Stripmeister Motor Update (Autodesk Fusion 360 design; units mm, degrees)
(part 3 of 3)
sketch "Sketch1" plane through (197.8083, 0, 0) normal (1, 0, 0) x axis (0, 1, 0)
  line L1 (0, 22.5) -> (0, 0)
  line L2 (3.5, 22.2261) -> (0, 0)
  line L3 (-3.5, 22.2261) -> (0, 0)
  circle C1 centre (0, 0) radius 17.907
  circle C2 centre (0, 0) radius 5.3594
  circle C3 centre (0, 0) radius 17.907
  circle C4 centre (0, 0) radius 18.669
  circle C5 centre (0, 0) radius 17.907
  circle C6 centre (0, 0) radius 22.5
  circle C7 centre (0, 0) radius 21.25
  point P5 (0, 0)
  point P7 (0, 0)
  point P8 (0, 22.5)
  point P3 (0, 0)
  point P9 (0, 0)
  point P10 (3.5, 22.2261)
  point P11 (0, 0)
  point P12 (-3.5, 22.2261)
  concentric C3 C6
  concentric C3 C7
  coincident P5 P7
  vertical L1
  coincident C6 P8
  coincident P3 P9
  coincident C6 P10
  coincident P5 P11
  coincident C6 P12
  dimension "d375" diameter C6 = 45
  dimension "d376" diameter C7 = 42.5
  dimension "d382" distance P8 P10 = 3.5
  dimension "d383" distance P8 P12 = 3.5
extrude "Extrude1" add sketch "Sketch1" profile of C6 C7 to an object from offset -30.5
extrude "Extrude2" add sketch "Sketch1" profile of C1 C3 C4 C5 C7 against normal blind 66
extrude "Extrude3" cut sketch "Sketch1" profile of C6 C7 L2 L3 against normal blind 66
sketch "Sketch1" plane through (0, 0, -12.7) normal (0, 0, -1) x axis (1, 0, 0)
  line L1 (12.7, 0.6112) -> (12.7, 32.7422)
  line L2 (-7.9375, -4.1513) -> (7.9375, -4.1513)
  line L3 (-12.7, 32.7422) -> (-12.7, 0.6112)
  line L4 (7.9375, 37.5047) -> (-7.9375, 37.5047)
  line L5 (-38.1, -66.8734) -> (-38.1, 66.8734)
  line L6 (38.1, 66.8734) -> (38.1, -66.8734)
  line L7 (-38.1, 74.7479) -> (-38.1, 66.8734)
  line L8 (-29.1639, 74.7479) -> (-38.1, 74.7479)
  line L9 (261.9, 74.7479) -> (-38.1, 74.7479)
  line L10 (261.9, -74.8109) -> (261.9, 74.7479)
  line L11 (-38.1, -74.8109) -> (261.9, -74.8109)
  line L12 (-38.1, 74.7479) -> (-38.1, -74.8109)
  arc A1 centre (7.9375, 0.6112) radius 4.7625 clockwise from (12.7, 0.6112) to (7.9375, -4.1513)
  arc A2 centre (-7.9375, 0.6112) radius 4.7625 clockwise from (-7.9375, -4.1513) to (-12.7, 0.6112)
  arc A3 centre (-7.9375, 32.7422) radius 4.7625 clockwise from (-12.7, 32.7422) to (-7.9375, 37.5047)
  arc A4 centre (7.9375, 32.7422) radius 4.7625 clockwise from (7.9375, 37.5047) to (12.7, 32.7422)
  circle C1 centre (0, -62.4919) radius 3.9687
  circle C2 centre (-28.575, 65.2859) radius 3.9687
  circle C3 centre (28.575, 65.2859) radius 3.9687
  circle C4 centre (0, -14.8669) radius 5.1594
  circle C5 centre (-22.225, 25.4) radius 5.1594
  circle C6 centre (-22.225, -25.4) radius 5.1594
  circle C7 centre (22.225, 25.4) radius 5.1594
  circle C8 centre (22.225, -25.4) radius 5.1594
  arc A5 centre (30.1625, 66.8734) radius 7.9375 clockwise from (29.1639, 74.7479) to (38.1, 66.8734)
  arc A6 centre (0, 304.7074) radius 231.8015 clockwise from (29.1639, 74.7479) to (-29.1639, 74.7479)
  arc A7 centre (-30.1625, 66.8734) radius 7.9375 clockwise from (-38.1, 66.8734) to (-29.1639, 74.7479)
  arc A8 centre (-30.1625, -66.8734) radius 7.9375 clockwise from (-29.1639, -74.7479) to (-38.1, -66.8734)
  arc A9 centre (0, -304.7074) radius 231.8015 clockwise from (-29.1639, -74.7479) to (29.1639, -74.7479)
  arc A10 centre (30.1625, -66.8734) radius 7.9375 clockwise from (38.1, -66.8734) to (29.1639, -74.7479)
  point P27 (-38.1, 66.8734)
  point P36 (-38.1, 66.8734)
  point P25 (-29.1639, 74.7479)
  point P38 (-29.1639, 74.7479)
  coincident P27 P36
  tangent A7 L7
  coincident P25 P38
  perpendicular L5 L8
  horizontal L9
  vertical L10
  horizontal L11
  vertical L12
  tangent A8 L11
  dimension "d386" distance L10 L12 = 300
extrude "Extrude1" new body sketch "Sketch1" profile of C1 C2 C3 L5 L9 L10 L11 L12 along normal blind 4
sketch "Sketch2" plane through (261.9, 0, 0) normal (1, 0, 0) x axis (0, 1, 0)
  line L1 (-74.7479, -12.7) -> (74.8109, -12.7)
  line L2 (-74.7479, -16.7) -> (-74.7479, -12.7)
  line L3 (74.8109, -16.7) -> (-74.7479, -16.7)
  line L4 (74.8109, -12.7) -> (74.8109, -16.7)
  line L5 (-3.5, 60.3261) -> (-3.3056, 59.0913)
  line L6 (3.3056, 59.0913) -> (3.5, 60.3261)
  line L7 (2.1583, 58.2346) -> (2.6644, 61.4485)
  line L8 (-2.6644, 61.4485) -> (-2.1583, 58.2346)
  line L9 (26, 38.1) -> (0, 38.1)
  line L10 (-26, 38.1) -> (0, 38.1)
  line L11 (-26, -12.7) -> (-26, 38.1)
  line L12 (26, -12.7) -> (26, 38.1)
  arc A1 centre (0, 38.1) radius 22.5 clockwise from (3.5, 60.3261) to (-3.5, 60.3261)
  arc A2 centre (0, 38.1) radius 21.25 clockwise from (3.3056, 59.0913) to (-3.3056, 59.0913)
  arc A3 centre (0, 38.1) radius 20.25 clockwise from (2.1583, 58.2346) to (-2.1583, 58.2346)
  arc A4 centre (0, 38.1) radius 23.5 clockwise from (2.6644, 61.4485) to (-2.6644, 61.4485)
  circle C1 centre (0, 38.1) radius 21.875
  circle C2 centre (0, 38.1) radius 1.5875
  circle C3 centre (0, 38.1) radius 23.5
  circle C4 centre (0, 38.1) radius 26
  point P16 (-2.6644, 61.4485)
  point P19 (0, 38.1)
  point P21 (0, 38.1)
  point P22 (26, 38.1)
  point P9 (0, 38.1)
  point P23 (0, 38.1)
  point P24 (-26, 38.1)
  point P25 (-26, -12.7)
  point P26 (26, -12.7)
  concentric A1 C1
  concentric A1 C3
  coincident P16 C3
  concentric C2 C4
  coincident P19 P21
  coincident C4 P22
  horizontal L9
  coincident P9 P23
  coincident C4 P24
  parallel L9 L10
  coincident L1 P25
  perpendicular L1 L11
  coincident L1 P26
  tangent C4 L12
  dimension "d389" = 1
  dimension "d390" diameter C1 = 43.75
  dimension "d391" diameter C4 = 52
extrude "Extrude2" sketch "Sketch2" profile of L1 L8 A4 L7 C1 C3 C4 L11 L12 blind -60
sketch "Sketch3" plane through (229.5433, 0, 0) normal (1, 0, 0) x axis (0, 1, 0)
  line L1 (-2.4114, 59.8417) -> (-2.6644, 61.4485)
  line L2 (2.6644, 61.4485) -> (2.4114, 59.8417)
  line L3 (26, -12.7) -> (-26, -12.7)
  line L4 (26, 38.1) -> (26, -12.7)
  line L5 (-26, -12.7) -> (-26, 38.1)
  line L6 (50, -12.7) -> (26, -12.7)
  line L7 (50, -6.7) -> (50, -12.7)
  line L8 (26, -6.7) -> (50, -6.7)
  line L9 (26, -12.7) -> (26, -6.7)
  line L10 (-50, -12.7) -> (-26, -12.7)
  line L11 (-50, -6.7) -> (-50, -12.7)
  line L12 (-26, -6.7) -> (-50, -6.7)
  line L13 (-26, -12.7) -> (-26, -6.7)
  line L14 (-30, -16.7) -> (-30, 38.1)
  line L15 (30, -16.7) -> (-30, -16.7)
  line L16 (30, 38.1) -> (30, -16.7)
  arc A1 centre (0, 38.1) radius 21.875 clockwise from (-2.4114, 59.8417) to (2.4114, 59.8417)
  arc A2 centre (0, 38.1) radius 23.5 clockwise from (2.6644, 61.4485) to (-2.6644, 61.4485)
  arc A3 centre (0, 38.1) radius 26 clockwise from (-26, 38.1) to (26, 38.1)
  arc A4 centre (0, 38.1) radius 30 clockwise from (-30, 38.1) to (30, 38.1)
  point P8 (26, -12.7)
  point P11 (26, -12.7)
  point P7 (-26, -12.7)
  point P15 (-26, -12.7)
  point P12 (50, -12.7)
  point P14 (26, -6.7)
  point P16 (-50, -12.7)
  point P18 (-26, -6.7)
  horizontal L6
  vertical L7
  horizontal L8
  vertical L9
  coincident P8 P11
  horizontal L10
  vertical L11
  horizontal L12
  vertical L13
  coincident P7 P15
  dimension "d395" distance P11 P12 = 24
  dimension "d396" distance P11 P14 = 6
  dimension "d397" distance P15 P16 = 24
  dimension "d398" distance P15 P18 = 6
  dimension "d399" = 4
extrude "Extrude3" add sketch "Sketch3" profile of L4 A3 L5 L6 L7 L8 L9 L10 L11 L12 L13 A4 L16 L14 against normal blind 60
sketch "Sketch4" plane through (0, 0, -6.7) normal (0, 0, 1) x axis (-1, 0, 0)
  line L1 (-229.5433, -50) -> (-229.5433, -30)
  line L2 (-169.5433, -50) -> (-229.5433, -50)
  line L3 (-169.5433, -30) -> (-169.5433, -50)
  line L4 (-229.5433, -30) -> (-169.5433, -30)
  line L5 (-229.5433, 30) -> (-229.5433, 50)
  line L6 (-169.5433, 30) -> (-229.5433, 30)
  line L7 (-169.5433, 50) -> (-169.5433, 30)
  line L8 (-229.5433, 50) -> (-169.5433, 50)
  line L9 (-199.5433, -50) -> (-199.5433, 50)
  line L10 (-230, 0) -> (-199.5433, 0)
  line L11 (-169.0866, 0) -> (-199.5433, 0)
  circle C1 centre (-217.5433, 42.5) radius 4
  circle C2 centre (-217.5433, 42.5) radius 7.5
  circle C3 centre (-181.5433, 42.5) radius 4
  circle C4 centre (-181.5433, 42.5) radius 7.5
  circle C5 centre (-181.5433, -42.5) radius 4
  circle C6 centre (-181.5433, -42.5) radius 7.5
  circle C7 centre (-217.5433, -42.5) radius 4
  circle C8 centre (-217.5433, -42.5) radius 7.5
  point P12 (-199.5433, 50)
  point P13 (-199.5433, -50)
  point P14 (-199.5433, 0)
  point P16 (-199.5433, 0)
  point P15 (-230, 0)
  point P17 (-169.0866, 0)
  point P11 (-217.5433, 42.5)
  concentric C1 C2
  tangent L8 C2
  midpoint L8 P12
  midpoint L2 P13
  midpoint L9 P14
  perpendicular L9 L10
  symmetric C1 L9 C3
  symmetric C2 L9 C4
  symmetric L9 P14 P16
  symmetric L9 P15 P17
  symmetric C1 L10 C7
  symmetric C2 L10 C8
  symmetric L10 C3 C5
  symmetric L10 C4 C6
  dimension "d402" diameter C1 = 8
  dimension "d403" diameter C2 = 15
  dimension "d404" distance L5 P11 = 12
extrude "Extrude4" cut sketch "Sketch4" profile of C1 C3 C5 C7 against normal blind 10
offset_faces "OffsetFaces1" distance 4
extrude "Extrude5" cut sketch "Sketch4" profile of C1 C2 C3 C4 C5 C6 C7 C8 against normal blind 2
sketch "Sketch5" plane through (229.5433, 0, 0) normal (1, 0, 0) x axis (0, 1, 0)
  line L1 (-2.4114, 59.8417) -> (-2.6644, 61.4485)
  line L2 (2.6644, 61.4485) -> (2.4114, 59.8417)
  line L3 (54, -12.7) -> (-54, -12.7)
  line L4 (54, -6.7) -> (54, -12.7)
  line L5 (30, -6.7) -> (54, -6.7)
  line L6 (30, 38.1) -> (30, -6.7)
  line L7 (-30, -6.7) -> (-30, 38.1)
  line L8 (-54, -6.7) -> (-30, -6.7)
  line L9 (-54, -12.7) -> (-54, -6.7)
  line L10 (50, -6.7) -> (35, -6.7)
  line L11 (50, -6.7) -> (35, -6.7)
  line L12 (54, -6.7) -> (30, -6.7)
  line L13 (30, -6.7) -> (54, -6.7)
  line L14 (0, -12.7) -> (0, 38.1)
  arc A1 centre (0, 38.1) radius 21.875 clockwise from (-2.4114, 59.8417) to (2.4114, 59.8417)
  arc A2 centre (0, 38.1) radius 23.5 clockwise from (2.6644, 61.4485) to (-2.6644, 61.4485)
  arc A3 centre (0, 38.1) radius 30 clockwise from (-30, 38.1) to (30, 38.1)
  arc A4 centre (233.204, 38.1) radius 203.204 clockwise from (35, -6.7) to (30, 38.1)
  arc A5 centre (-233.204, 38.1) radius 203.204 clockwise from (-30, 38.1) to (-35, -6.7)
  point P11 (30, 38.1)
  point P20 (30, 38.1)
  point P15 (35, -6.7)
  point P19 (35, -6.7)
  point P5 (0, 38.1)
  point P22 (0, 38.1)
  point P26 (-35, -6.7)
  point P25 (-30, 38.1)
  tangent L6 A4
  coincident P11 P20
  coincident P15 P19
  coincident P5 P22
  perpendicular L3 L14
  symmetric P19 L14 P26
  symmetric P20 L14 P25
  symmetric A4 L14 A5
extrude "Extrude6" add sketch "Sketch5" profile of L5 L6 L7 L8 L12 L13 A4 A5 against normal blind 60
fillet "Fillet1" radius 8
work_plane "WorkPlane1"
work_plane "WorkPlane2" AlongDistance 2
work_plane "WorkPlane1" AlongDistance -61
work_plane "WorkPlane2" AlongDistance -29
work_plane "WorkPlane3" AlongDistance -11
split "Split1"
align "Align1"
extrude "Extrude4" add of existing geometry blind 22
sketch "Sketch2" plane through (167.3083, 0, 0) normal (1, 0, 0) x axis (0, 1, 0)
  line L1 (-2.4114, 21.7417) -> (-2.6644, 23.3485)
  line L2 (2.6644, 23.3485) -> (2.4114, 21.7417)
  line L3 (-46, -50.8) -> (-46, -44.8)
  line L4 (46, -50.8) -> (-46, -50.8)
  line L5 (46, -44.8) -> (46, -50.8)
  line L6 (35, -44.8) -> (46, -44.8)
  line L7 (-46, -44.8) -> (-35, -44.8)
  line L8 (-54, -50.8) -> (-46, -50.8)
  line L9 (-46, -50.8) -> (46, -50.8)
  line L10 (46, -50.8) -> (54, -50.8)
  line L11 (-46, -44.8) -> (-54, -44.8)
  line L12 (-54, -44.8) -> (-54, -50.8)
  line L13 (-2.6644, 23.3485) -> (-2.4114, 21.7417)
  line L14 (2.4114, 21.7417) -> (2.6644, 23.3485)
  line L15 (-35, -44.8) -> (-46, -44.8)
  line L16 (46, -44.8) -> (35, -44.8)
  line L17 (54, -50.8) -> (54, -44.8)
  line L18 (54, -44.8) -> (46, -44.8)
  line L19 (27.1878, 12.6817) -> (54, -44.8)
  line L20 (-27.1878, 12.6817) -> (-54, -44.8)
  arc A1 centre (0, 0) radius 21.875 clockwise from (-2.4114, 21.7417) to (2.4114, 21.7417)
  arc A2 centre (0, 0) radius 23.5 clockwise from (2.6644, 23.3485) to (-2.6644, 23.3485)
  arc A3 centre (233.204, 0) radius 203.204 clockwise from (35, -44.8) to (30, 0)
  arc A4 centre (0, 0) radius 30 clockwise from (-30, 0) to (30, 0)
  arc A5 centre (-233.204, 0) radius 203.204 clockwise from (-30, 0) to (-35, -44.8)
  arc A6 centre (0, 0) radius 23.5 clockwise from (2.6644, 23.3485) to (-2.6644, 23.3485)
  arc A7 centre (0, 0) radius 21.875 clockwise from (-2.4114, 21.7417) to (2.4114, 21.7417)
  arc A8 centre (-233.204, 0) radius 203.204 clockwise from (-30, 0) to (-35, -44.8)
  arc A9 centre (0, 0) radius 30 clockwise from (-30, 0) to (30, 0)
  arc A10 centre (233.204, 0) radius 203.204 clockwise from (35, -44.8) to (30, 0)
  point P35 (54, -44.8)
  point P36 (54, -44.8)
  point P37 (27.1878, 12.6817)
  point P21 (-54, -44.8)
  point P38 (-54, -44.8)
  point P39 (-27.1878, 12.6817)
  coincident P35 P36
  coincident A4 P37
  tangent A4 L19
  coincident P21 P38
  coincident A4 P39
  tangent A4 L20
extrude "Extrude7" sketch "Sketch2" profile of L6 A3 A4 A5 L7 L11 L15 A8 A9 A10 L16 L18 L19 L20 blind 3
base_feature "Base Feature1" bodies "Motor", "Gearbox", "Chuck Bottom", "Chuck Top"
base_feature "Base Feature1" bodies "Mount Spacer Stripmeister", "Mount Spacer"
base_feature "Base Feature1" bodies "Drill Motor Train Mount v1", "Drill Motor Train Mount v2 Standoff"
base_feature "Base Feature1" bodies "B Half", "B Half (1)"
base_feature "Base Feature1" bodies "Mount Plate Bracket C v2", "Mount Plate Bracket C"
place_component sketch "Sketch1"
base_feature "Base Feature1" sketch "Sketch1" bodies "Mount Plate Bracket D"
base_feature "Base Feature1"
delete_face "DeleteFace1"
delete_face "DeleteFace2"
position "Position11"
extrude "Extrude1" new body of existing geometry blind 4
offset_faces "OffsetFaces1" distance 4
combine "Combine1"
as_built_joint "As-built2"
position "Position12"
position "Position13"
extrude "Extrude2" cut of existing geometry blind -2.304
delete_face "DeleteFace1"
delete_face "DeleteFace2"
delete_face "DeleteFace3"
delete_face "DeleteFace4"
sketch "Sketch6" plane through (0, 0, -16.7) normal (0, 0, -1) x axis (1, 0, 0)
  line L1 (133.575, 45.6447) -> (133.575, 31.25)
  line L2 (133.575, 45.6447) -> (195.575, 45.6447)
  line L3 (195.575, -45.6447) -> (195.575, 45.6447)
  line L4 (133.575, 31.25) -> (133.575, -31.25)
  line L5 (195.575, -45.6447) -> (133.575, -45.6447)
  line L6 (133.575, -45.6447) -> (133.575, -31.25)
  circle C1 centre (164.575, -37.6447) radius 2
  circle C2 centre (164.575, 37.6447) radius 2
  circle C3 centre (144.575, -37.6447) radius 2
  circle C4 centre (144.575, 37.6447) radius 2
extrude "Extrude8" cut sketch "Sketch6" profile of C1 C2 C3 C4 against normal blind 4
offset_faces "OffsetFaces2" distance -1
sketch "Sketch7" plane through (0, 0, -15.7) normal (0, 0, -1) x axis (1, 0, 0)
  line L1 (-38.1, 74.7479) -> (-38.1, -74.8109)
  line L2 (261.9, 74.7479) -> (-38.1, 74.7479)
  line L3 (261.9, -74.8109) -> (261.9, 74.7479)
  line L4 (-38.1, -74.8109) -> (261.9, -74.8109)
  line L5 (129.575, 37.6447) -> (144.575, 37.6447)
  line L6 (129.575, -37.6447) -> (144.575, -37.6447)
  line L7 (184.575, 35.6447) -> (129.575, 35.6447)
  line L8 (129.575, 39.6447) -> (184.575, 39.6447)
  line L9 (184.575, 37.6447) -> (129.575, 37.6447)
  line L10 (184.575, -39.6447) -> (129.575, -39.6447)
  line L11 (129.575, -35.6447) -> (184.575, -35.6447)
  line L12 (184.575, -37.6447) -> (129.575, -37.6447)
  line L13 (-31.75, -68.4609) -> (255.55, -68.4609)
  line L14 (-31.75, 68.3979) -> (-31.75, -68.4609)
  line L15 (255.55, 68.3979) -> (-31.75, 68.3979)
  line L16 (255.55, -68.4609) -> (255.55, 68.3979)
  line L17 (-28.575, 65.2859) -> (28.575, 65.2859)
  line L18 (0, 30) -> (0, 65.2859)
  circle C1 centre (144.575, -37.6447) radius 2
  circle C2 centre (164.575, -37.6447) radius 2
  circle C3 centre (164.575, 37.6447) radius 2
  circle C4 centre (144.575, 37.6447) radius 2
  circle C5 centre (-28.575, 65.2859) radius 3.9687
  circle C6 centre (28.575, 65.2859) radius 3.9687
  circle C7 centre (0, -62.4919) radius 3.9687
  arc A1 centre (184.575, 37.6447) radius 2 clockwise from (184.575, 39.6447) to (184.575, 35.6447)
  arc A2 centre (129.575, 37.6447) radius 2 clockwise from (129.575, 35.6447) to (129.575, 39.6447)
  arc A3 centre (184.575, -37.6447) radius 2 clockwise from (184.575, -35.6447) to (184.575, -39.6447)
  arc A4 centre (129.575, -37.6447) radius 2 clockwise from (129.575, -39.6447) to (129.575, -35.6447)
  circle C8 centre (242.85, 55.6979) radius 12.7
  circle C9 centre (242.85, -55.7609) radius 12.7
  circle C10 centre (-19.05, -55.7609) radius 12.7
  circle C11 centre (0, 55.6979) radius 12.7
  circle C12 centre (0, 55.6979) radius 2
  circle C13 centre (-19.05, -55.7609) radius 2
  circle C14 centre (242.85, -55.7609) radius 2
  circle C15 centre (242.85, 55.6979) radius 2
  point P5 (144.575, 37.6447)
  point P13 (144.575, 37.6447)
  point P2 (144.575, -37.6447)
  point P15 (144.575, -37.6447)
  point P14 (129.575, 37.6447)
  point P21 (129.575, 37.6447)
  point P16 (129.575, -37.6447)
  point P27 (129.575, -37.6447)
  point P7 (28.575, 65.2859)
  point P37 (28.575, 65.2859)
  point P6 (-28.575, 65.2859)
  point P38 (-28.575, 65.2859)
  point P39 (0, 65.2859)
  point P32 (0, 55.6979)
  point P28 (184.575, -37.6447)
  point P4 (164.575, 37.6447)
  point P22 (184.575, 37.6447)
  coincident P5 P13
  horizontal L5
  coincident P2 P15
  horizontal L6
  tangent L7 A1
  tangent A1 L8
  parallel L7 L8
  tangent L8 A2
  tangent L7 A2
  parallel L5 L9
  coincident P14 P21
  tangent L10 A3
  tangent A3 L11
  parallel L10 L11
  tangent L11 A4
  tangent L10 A4
  parallel L6 L12
  coincident P16 P27
  tangent C11 L15
  tangent C10 L13
  tangent C10 L14
  tangent C8 L15
  tangent C8 L16
  tangent C9 L16
  tangent C9 L13
  coincident P7 P37
  coincident P6 P38
  midpoint L17 P39
  perpendicular L17 L18
  coincident P32 L18
  concentric C11 C12
  concentric C10 C13
  concentric C9 C14
  concentric C8 C15
  dimension "d433" distance P13 P14 = 15
  dimension "d434" distance P15 P16 = 15
  dimension "d435" diameter A1 = 4
  dimension "d436" distance P27 P28 = 55
  dimension "d437" diameter A3 = 4
  dimension "d438" distance P4 P22 = 20
  dimension "d441" diameter C8 = 25.4
  dimension "d442" diameter C9 = 25.4
  dimension "d443" diameter C10 = 25.4
  dimension "d444" diameter C11 = 25.4
  dimension "d445" = 6.35
  dimension "d446" diameter C12 = 4
  dimension "d447" diameter C13 = 4
  dimension "d448" diameter C14 = 4
  dimension "d449" diameter C15 = 4
extrude "Extrude9" cut sketch "Sketch7" profile of C1 C2 C3 C4 L7 A1 L8 A2 L10 A3 L11 A4 against normal blind 3
extrude "Extrude10" cut sketch "Sketch7" profile of C12 C13 C14 C15 against normal blind 3
extrude "Extrude1" new body sketch "Sketch7" profile of C11 C12 along normal blind 12.7
extrude "Extrude2" new body sketch "Sketch7" profile of C8 C9 C10 C13 C14 C15 along normal blind 12.7
fillet "Fillet1" radius 3
sketch "Sketch1" plane through (0, 0, -28.4) normal (0, 0, -1) x axis (1, 0, 0)
  circle C1 centre (0, 55.6979) radius 12.7
  circle C2 centre (0, 55.6979) radius 2
  circle C3 centre (242.85, 55.6979) radius 12.7
  circle C4 centre (242.85, 55.6979) radius 2
  circle C5 centre (242.85, -55.7609) radius 12.7
  circle C6 centre (242.85, -55.7609) radius 2
  circle C7 centre (-19.05, -55.7609) radius 12.7
  circle C8 centre (-19.05, -55.7609) radius 2
  circle C9 centre (-19.05, -55.7609) radius 5
  circle C10 centre (0, 55.6979) radius 5
  circle C11 centre (242.85, 55.6979) radius 5
  circle C12 centre (242.85, -55.7609) radius 5
  concentric C7 C9
  concentric C1 C10
  concentric C3 C11
  concentric C5 C12
  dimension "d458" diameter C9 = 10
  dimension "d459" diameter C10 = 10
  dimension "d460" diameter C11 = 10
  dimension "d461" diameter C12 = 10
extrude "Extrude3" cut sketch "Sketch1" profile of C2 C4 C6 C8 C9 C10 C11 C12 against normal blind 10
fillet "Fillet2" radius 2
sketch "Sketch1" plane through (0, 50.7996, 0) normal (0, 1, 0) x axis (-1, 0, 0)
  line L1 (22.1717, 86.2441) -> (22.1717, 63.5)
  line L2 (4.7072, 114.5) -> (4.7072, 110.5)
  line L3 (-4.7072, 114.5) -> (4.7072, 114.5)
  line L4 (-4.7072, 110.5) -> (-4.7072, 114.5)
  line L5 (-22.1716, 63.5) -> (-22.1716, 86.2441)
  line L6 (22.1717, 63.5) -> (-22.1716, 63.5)
  line L7 (-2, 96.5) -> (2, 96.5)
  line L8 (2, 96.5) -> (11, 87.5)
  line L9 (11, 79.5) -> (11, 87.5)
  line L10 (11, 79.5) -> (7, 71.5)
  line L11 (7, 71.5) -> (-7, 71.5)
  line L12 (-7, 71.5) -> (-11, 79.5)
  line L13 (-11, 87.5) -> (-11, 79.5)
  line L14 (-11, 87.5) -> (-2, 96.5)
  line L15 (11, 83.5) -> (-11, 83.5)
  line L16 (-22.2766, 71.5) -> (22.2766, 71.5)
  line L17 (-9, 95.5) -> (9, 95.5)
  line L18 (-13, 75.5) -> (-13, 91.5)
  line L19 (9, 71.5) -> (-9, 71.5)
  line L20 (13, 91.5) -> (13, 75.5)
  line L21 (-13, 71.5) -> (13, 95.5)
  line L22 (13, 71.5) -> (-13, 95.5)
  closed curve K1 centre (0, 25.3282)
  closed curve K2 centre (0, 25.3282)
  arc A1 centre (-9, 91.5) radius 4 clockwise from (-13, 91.5) to (-9, 95.5)
  arc A2 centre (9, 91.5) radius 4 clockwise from (9, 95.5) to (13, 91.5)
  arc A3 centre (9, 75.5) radius 4 clockwise from (13, 75.5) to (9, 71.5)
  arc A4 centre (-9, 75.5) radius 4 clockwise from (-9, 71.5) to (-13, 75.5)
  point P20 (-11, 83.5)
  point P21 (11, 83.5)
  point P28 (0, 83.5)
  point P25 (-13, 95.5)
  point P24 (13, 95.5)
  point P27 (13, 71.5)
  point P26 (-13, 71.5)
  midpoint L13 P20
  midpoint L9 P21
  horizontal L17
  perpendicular L17 L18
  parallel L17 L19
  parallel L18 L20
  coincident L21 P28
  coincident L22 P28
  midpoint L15 P28
  coincident P25 L18
  coincident P25 L17
  tangent L18 A1
  tangent L17 A1
  coincident P24 L17
  coincident P24 L20
  tangent L17 A2
  tangent L20 A2
  equal A1 A2
  coincident P27 L20
  coincident P27 L19
  tangent L20 A3
  tangent L19 A3
  equal A1 A3
  coincident P26 L19
  coincident P26 L18
  tangent L19 A4
  tangent L18 A4
  equal A1 A4
  dimension "d466" distance P26 P27 = 26
  dimension "d467" distance P25 P26 = 24
  dimension "d468" radius A1 = 4
extrude "Extrude1" cut sketch "Sketch1" profile of L17 L18 L19 L20 A1 A2 A3 A4 along a picked direction blind -14.83
extrude "Extrude3" cut sketch "Sketch1" profile of L17 L18 L19 L20 A1 A2 A3 A4 along a picked direction blind -4.83
sketch "Sketch2" plane through (0, 0, 89.5) normal (0, 0, -1) x axis (1, 0, 0)
  line L1 (10.409, 47.1792) -> (11.4674, 45.6447)
  line L2 (-11.4674, 45.6447) -> (-10.4096, 47.1783)
  line L3 (-18.6447, 45.6447) -> (-11.4674, 45.6447)
  line L4 (-45.6447, 6.8741) -> (-45.6447, 18.6447)
  line L5 (-31.25, 16.8401) -> (-45.0501, 7.322)
  line L6 (-31.25, 25) -> (-31.25, 16.8401)
  line L7 (-16.8401, 31.25) -> (-25, 31.25)
  line L8 (-7.3225, 45.0493) -> (-16.8401, 31.25)
  line L9 (16.8401, 31.25) -> (7.322, 45.0501)
  line L10 (25, 31.25) -> (16.8401, 31.25)
  line L11 (31.25, 16.8401) -> (31.25, 25.0008)
  line L12 (45.0509, 7.3214) -> (31.25, 16.8401)
  line L13 (45.6447, 18.6447) -> (45.6447, 6.8741)
  line L14 (11.4674, 45.6447) -> (18.6447, 45.6447)
  line L15 (11.3361, 45.3947) -> (18.6447, 45.3947)
  line L16 (10.2032, 47.0373) -> (11.3361, 45.3947)
  line L17 (-11.3361, 45.3947) -> (-10.2038, 47.0363)
  line L18 (-18.6447, 45.3947) -> (-11.3361, 45.3947)
  line L19 (-45.3947, 7.3839) -> (-45.3947, 18.6447)
  line L20 (-31.5, 16.9714) -> (-45.192, 7.5278)
  line L21 (-31.5, 25) -> (-31.5, 16.9714)
  line L22 (-16.9714, 31.5) -> (-25, 31.5)
  line L23 (-7.5283, 45.1912) -> (-16.9714, 31.5)
  line L24 (16.9714, 31.5) -> (7.5278, 45.192)
  line L25 (25, 31.5) -> (16.9714, 31.5)
  line L26 (31.5, 16.9714) -> (31.5, 25.0008)
  line L27 (45.1929, 7.5272) -> (31.5, 16.9714)
  line L28 (45.3947, 18.6447) -> (45.3947, 7.3839)
  line L29 (48.6329, 5.1546) -> (31.5, 16.9714)
  line L30 (-47.1009, 6.2112) -> (-31.5, 16.9714)
  arc A1 centre (0, 40) radius 12.6447 clockwise from (-10.4096, 47.1783) to (10.409, 47.1792)
  arc A2 centre (-18.6447, 18.6447) radius 27 clockwise from (-45.6447, 18.6447) to (-18.6447, 45.6447)
  arc A3 centre (-40, 0) radius 8.8947 clockwise from (-45.6447, 6.8741) to (-45.0501, 7.322)
  arc A4 centre (-25, 25) radius 6.25 clockwise from (-31.25, 25) to (-25, 31.25)
  arc A5 centre (0, 40) radius 8.8947 clockwise from (-7.3225, 45.0493) to (7.322, 45.0501)
  arc A6 centre (25, 25) radius 6.25 clockwise from (25, 31.25) to (31.25, 25.0008)
  arc A7 centre (40, 0) radius 8.8947 clockwise from (45.0509, 7.3214) to (45.6447, 6.8741)
  arc A8 centre (18.6447, 18.6447) radius 27 clockwise from (18.6447, 45.6447) to (45.6447, 18.6447)
  arc A9 centre (0, 40) radius 12.3947 clockwise from (-10.2038, 47.0363) to (10.2032, 47.0373)
  arc A10 centre (-18.6447, 18.6447) radius 26.75 clockwise from (-45.3947, 18.6447) to (-18.6447, 45.3947)
  arc A11 centre (-40, 0) radius 9.1447 clockwise from (-45.3947, 7.3839) to (-45.192, 7.5278)
  arc A12 centre (-25, 25) radius 6.5 clockwise from (-31.5, 25) to (-25, 31.5)
  arc A13 centre (0, 40) radius 9.1447 clockwise from (-7.5283, 45.1912) to (7.5278, 45.192)
  arc A14 centre (25, 25) radius 6.5 clockwise from (25, 31.5) to (31.5, 25.0008)
  arc A15 centre (40, 0) radius 9.1447 clockwise from (45.1929, 7.5272) to (45.3947, 7.3839)
  arc A16 centre (18.6447, 18.6447) radius 26.75 clockwise from (18.6447, 45.3947) to (45.3947, 18.6447)
  parallel L27 L29
  parallel L20 L30
  dimension "d475" = -0.25
extrude "Extrude2" cut sketch "Sketch2" profile of L4 A3 L5 L6 A4 L7 L8 A5 L9 L10 A6 L11 L12 A7 L13 A15 A14 L24 L23 L22 L20 A12 L25 L21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 along a picked direction blind -25
remove_instance "RemoveInstance6"
remove_instance "RemoveInstance1"
fillet "Fillet6" radius 1.27
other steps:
base_feature "Base Feature1"
base_feature "Base Feature1"
base_feature "Base Feature2"
base_feature "Base Feature2"
extrude "Extrude1" cut sketch "Sketch1" profile of L17 L18 L19 L20 A1 A2 A3 A4 along a picked direction blind -14.83
base_feature "Base Feature3"
base_feature "Base Feature4"
base_feature "Base Feature2"
base_feature "Base Feature3"
base_feature "Base Feature4"
create_component "CreateComponent1"
create_component "CreateComponent2"
create_component "CreateComponent3"
create_component "CreateComponent4"
remove_body "RemoveBody1"
create_component "CreateComponent5"
remove_body "RemoveBody1"
create_component "CreateComponent1"
create_component "CreateComponent1"
create_component "CreateComponent6"
create_component "CreateComponent1"
create_component "CreateComponent7"
create_component "CreateComponent8"
create_component "CreateComponent9"
create_component "CreateComponent1"
create_component "CreateComponent2"
create_component "CreateComponent1"
create_component "CreateComponent10"
remove_instance "RemoveInstance1"
remove_instance "RemoveInstance2"
remove_instance "RemoveInstance3"
remove_instance "RemoveInstance4"
remove_instance "RemoveInstance5"
create_component "CreateComponent11"
create_component "CreateComponent12"
create_component "CreateComponent13"
create_component "CreateComponent1"
create_component "CreateComponent2"
create_component "CreateComponent1"
create_component "CreateComponent2"
create_component "CreateComponent3"
create_component "CreateComponent4" sketch "Sketch1"
create_component "CreateComponent3"
create_component "CreateComponent1"
named bodies: "Wheel Block", "Wheel Pin", "Locking Pin", "Wheel Screw", "Cutter Wheel", "Knob", "Knob (1)", "Motor", "Gearbox", "Chuck Bottom", "Chuck Top", "Drill Motor Train Mount v1", "Drill Motor Train Mount v2 Standoff", "B Half", "B Half (1)", "Mount Plate Bracket C v2", "Mount Plate Bracket D", "Mount Spacer Stripmeister", "Mount Spacer", "Mount Plate Bracket C"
